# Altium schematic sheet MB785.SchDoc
size A4; Revision: A.1(PCB.SCH)
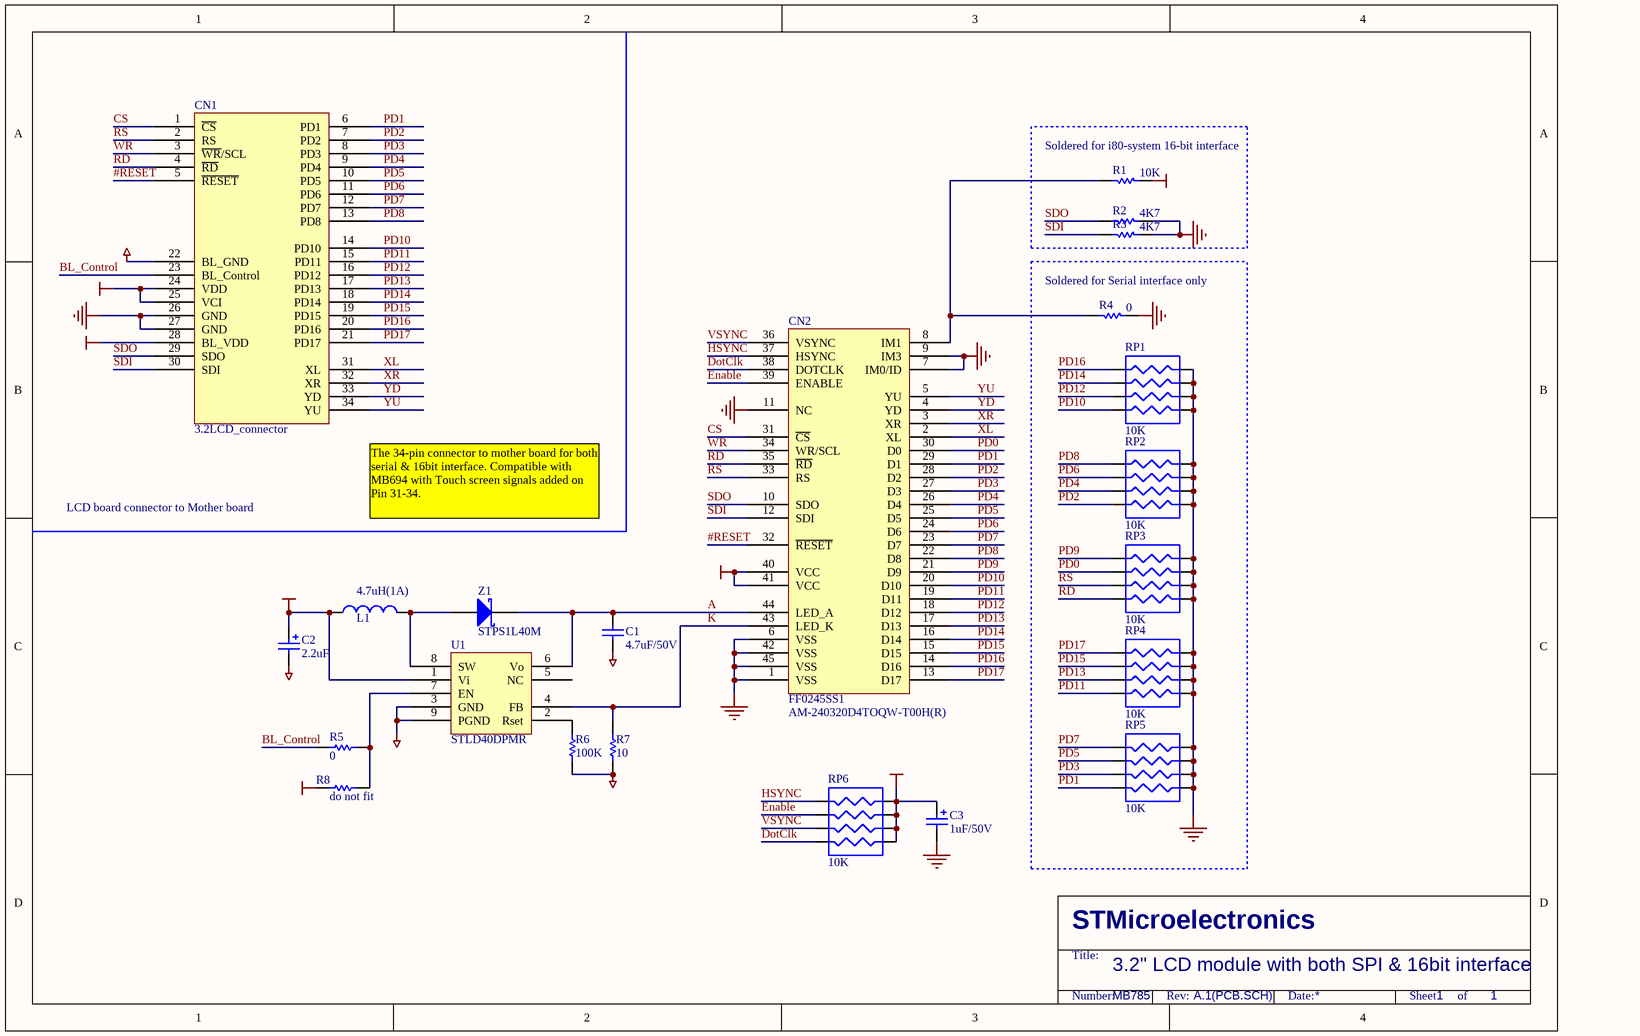
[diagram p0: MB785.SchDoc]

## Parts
C1  4.7uF/50V  [TAN-B]
C2  2.2uF  [TAN-A]
C3  1uF/50V  [TAN-B]
CN1  3.2LCD_connector  [2*17P]
CN2  FF0245SS1  [FF0245SS1]
L1  4.7uH(1A)  [3225]
R1  10K  [0603R]
R2  4K7  [0603R]
R3  4K7  [0603R]
R4  0  [0603R]
R5  0  [0603R]
R6  100K  [0603R]
R7  10  [0603R]
R8  do not fit  [0603R]
RP1  10K  [RES4B]
RP2  10K  [RES4B]
RP3  10K  [RES4B]
RP4  10K  [RES4B]
RP5  10K  [RES4B]
RP6  10K  [RES4B]
U1  STLD40DPMR  [QFNT8]
Z1  STPS1L40M  [DO216AA]

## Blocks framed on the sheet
Soldered for i80-system 16-bit interface: R1-R3

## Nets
BLGND: C1.1 C2.2 CN1.22(BL_GND) R6.2 R7.1 U1.3(GND) U1.9(PGND)
BLVDD: C2.1 CN1.28(BL_VDD) L1.1 R8.2 U1.1(Vi)
GND: C3.2 CN1.26(GND) CN1.27(GND) CN2.1(VSS) CN2.6(VSS) CN2.7(IM0/ID) CN2.9(IM3) CN2.11(NC) CN2.42(VSS) CN2.45(VSS) R2.1 R3.1 R4.2 RP1.2(R1) RP1.4(R3) RP1.6(R2) RP1.8(R0) RP2.2(R1) RP2.4(R3) RP2.6(R2) RP2.8(R0) RP3.2(R1) RP3.4(R3) RP3.6(R2) RP3.8(R0) RP4.2(R1) RP4.4(R3) RP4.6(R2) RP4.8(R0) RP5.2(R1) RP5.4(R3) RP5.6(R2) RP5.8(R0)
VDD: C3.1 CN1.24(VDD) CN1.25(VCI) CN2.40(VCC) CN2.41(VCC) R1.2 RP6.2(R1) RP6.4(R3) RP6.6(R2) RP6.8(R0)
#RESET: CN1.5(~{RESET}) CN2.32(~{RESET})
A: C1.2 CN2.44(LED_A) U1.6(Vo) Z1.2(K)
BL_Control: CN1.23(BL_Control) R5.2
CS: CN1.1(~{CS}) CN2.31(~{CS})
DotClk: CN2.38(DOTCLK) RP6.1(R0)
Enable: CN2.39(ENABLE) RP6.5(R3)
HSYNC: CN2.37(HSYNC) RP6.7(R1)
K: CN2.43(LED_K) R7.2 U1.4(FB)
PD0: CN2.30(D0) RP3.3(R2)
PD1: CN1.6(PD1) CN2.29(D1) RP5.1(R0)
PD2: CN1.7(PD2) CN2.28(D2) RP2.7(R1)
PD3: CN1.8(PD3) CN2.27(D3) RP5.3(R2)
PD4: CN1.9(PD4) CN2.26(D4) RP2.5(R3)
PD5: CN1.10(PD5) CN2.25(D5) RP5.5(R3)
PD6: CN1.11(PD6) CN2.24(D6) RP2.3(R2)
PD7: CN1.12(PD7) CN2.23(D7) RP5.7(R1)
PD8: CN1.13(PD8) CN2.22(D8) RP2.1(R0)
PD9: CN2.21(D9) RP3.1(R0)
PD10: CN1.14(PD10) CN2.20(D10) RP1.7(R1)
PD11: CN1.15(PD11) CN2.19(D11) RP4.7(R1)
PD12: CN1.16(PD12) CN2.18(D12) RP1.5(R3)
PD13: CN1.17(PD13) CN2.17(D13) RP4.5(R3)
PD14: CN1.18(PD14) CN2.16(D14) RP1.3(R2)
PD15: CN1.19(PD15) CN2.15(D15) RP4.3(R2)
PD16: CN1.20(PD16) CN2.14(D16) RP1.1(R0)
PD17: CN1.21(PD17) CN2.13(D17) RP4.1(R0)
RD: CN1.4(~{RD}) CN2.35(~{RD}) RP3.7(R1)
RS: CN1.2(RS) CN2.33(RS) RP3.5(R3)
SDI: CN1.30(SDI) CN2.12(SDI) R3.2
SDO: CN1.29(SDO) CN2.10(SDO) R2.2
VSYNC: CN2.36(VSYNC) RP6.3(R2)
WR: CN1.3(~{WR}/SCL) CN2.34(WR/SCL)
XL: CN1.31(XL) CN2.2(XL)
XR: CN1.32(XR) CN2.3(XR)
YD: CN1.33(YD) CN2.4(YD)
YU: CN1.34(YU) CN2.5(YU)
NetCN2_8: CN2.8(IM1) R1.1 R4.1
NetL1_2: L1.2 U1.8(SW) Z1.1(A)
NetR5_1: R5.1 R8.1 U1.7(EN)
NetR6_1: R6.1 U1.2(Rset)

Not connected (* = marked no-connect by the designer): U1 5(NC)

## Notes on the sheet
- Soldered for Serial interface only
- LCD board connector to Mother board
- (near CN1) The 34-pin connector to mother board for both serial & 16bit interface. Compatible with MB694 with Touch screen signals added on Pin 31-34.
- (near CN2) AM-240320D4TOQW-T00H(R)
- 3.2" LCD module with both SPI & 16bit interface
- MB785
- 1

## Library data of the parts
C1 = CAP: Capacitor; Value: 100pF
C2 C3 = Cap Pol1: Polarized Capacitor (Radial); Value: 100pF
L1 = Inductor: Value: 100uH
R1-R8 = Res1: Resistor; Value: 1K
RP1-RP6 = RES4B
Z1 = D Schottky: Schottky Diode; Code - JEDEC: DO-214-AA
